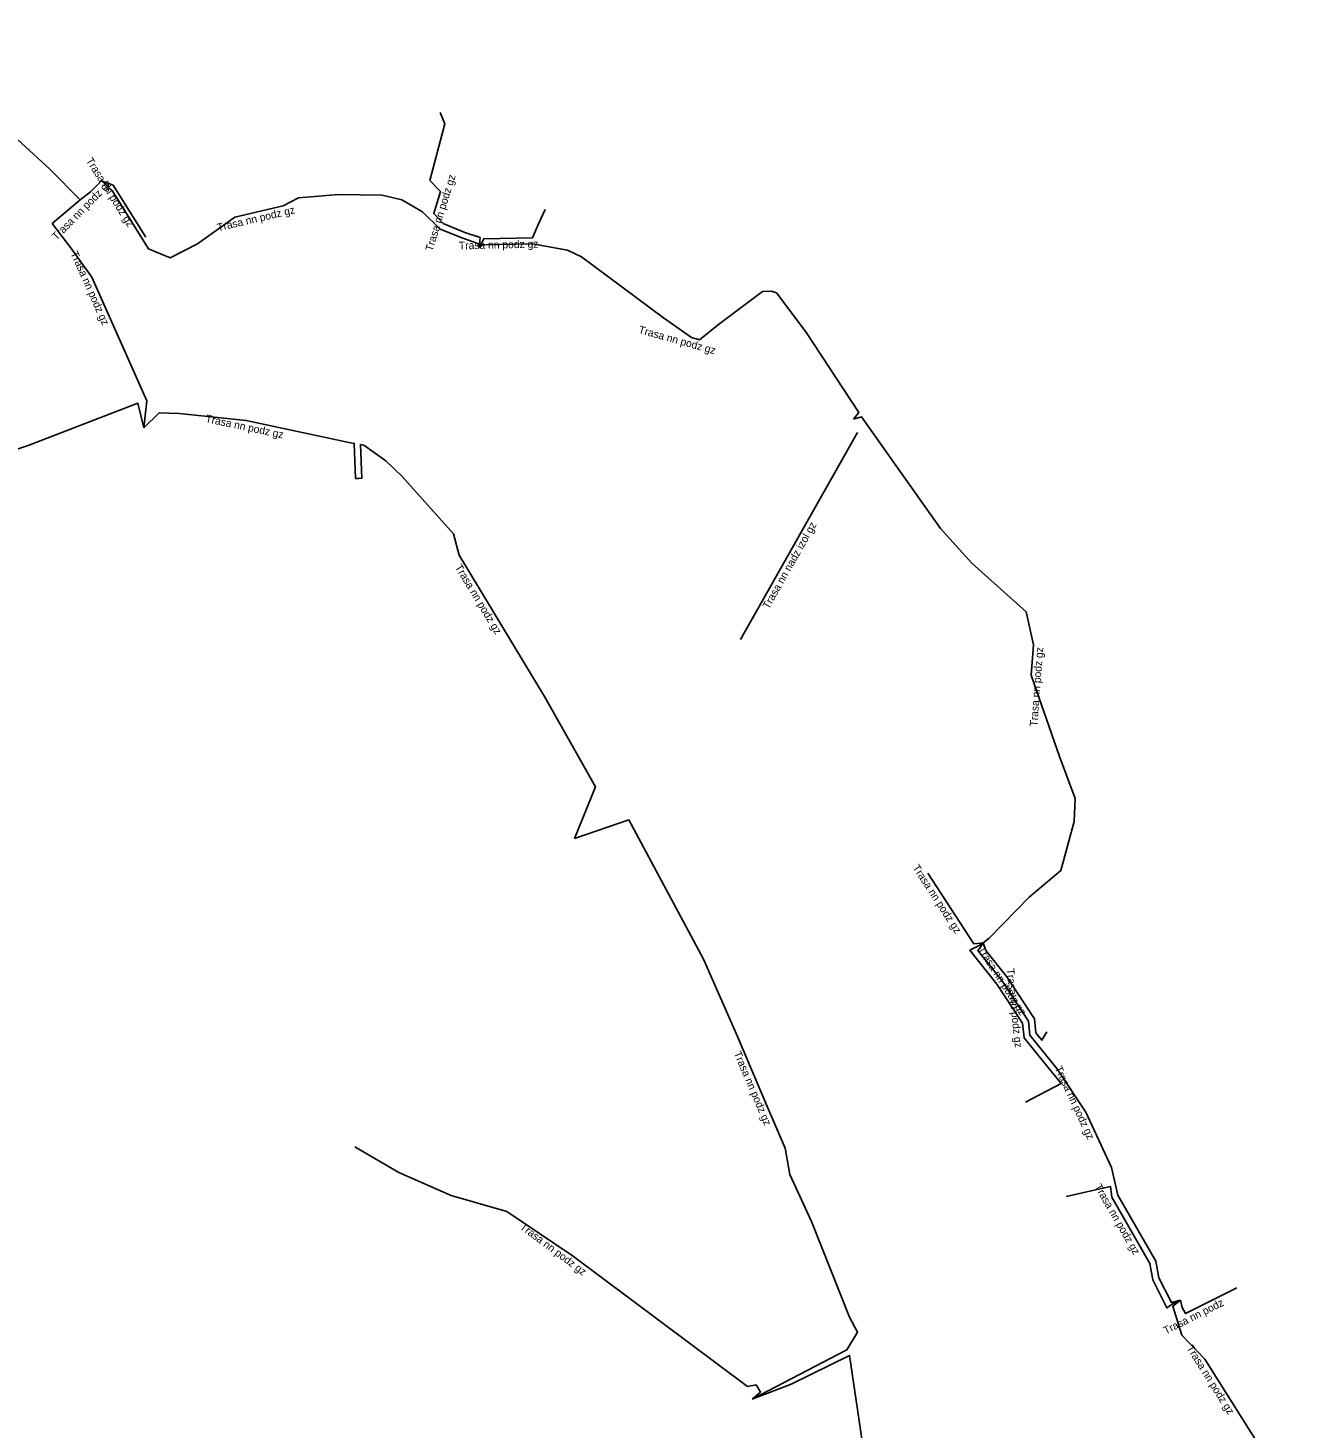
# Model space of a CAD drawing. Extents: x -484846 to -484244, y -1128177 to -1127608.
# Drawn here: x -484754.1 to -484671.6, y -1127724.5 to -1127633.5 of the extents above; entities that cross this region are included whole.
import ezdxf

# ---------------------------------------------------------------- set-up
doc = ezdxf.new("R2010")
doc.units = 0
doc.layers.add('Popiskový text - Ostatní atributy Trasy', color=7, linetype='Continuous')
doc.layers.add('Spojnice NN', color=7, linetype='Continuous')

msp = doc.modelspace()

# ---------------------------------------------------------------- linework, layer by layer
at = {"layer": 'Spojnice NN'}
for points in [[(-484761.387, -1127633.535), (-484759.01, -1127636.37), (-484755.62, -1127640.04), (-484752.72, -1127642.7), (-484750.74, -1127644.7)], [(-484724.81, -1127647.796), (-484724.758, -1127647.149), (-484725.74, -1127646.813), (-484727.151, -1127646.244), (-484727.767, -1127645.587), (-484727.33, -1127644.16), (-484728.02, -1127643.45), (-484727.05, -1127639.77), (-484727.341, -1127639.028)], [(-484750.74, -1127644.7), (-484750.06, -1127644.19), (-484749.35, -1127643.47)], [(-484724.81, -1127647.796), (-484724.894, -1127647.54), (-484725.88, -1127647.187), (-484727.349, -1127646.596), (-484728.5, -1127645.49), (-484729.83, -1127644.71), (-484731.12, -1127644.39), (-484733.98, -1127644.36), (-484734.73, -1127644.42), (-484736.56, -1127644.58), (-484737.55, -1127645.09), (-484740.69, -1127645.83), (-484743.11, -1127647.55), (-484744.9, -1127648.47), (-484746.29, -1127647.89), (-484748.656, -1127644.084), (-484749.35, -1127643.47)], [(-484749.35, -1127643.47), (-484748.606, -1127643.743), (-484746.469, -1127647.115)], [(-484750.74, -1127644.7), (-484752.57, -1127646.24), (-484751.3, -1127647.89), (-484749.98, -1127649.72), (-484746.419, -1127657.755), (-484746.597, -1127659.523)], [(-484724.81, -1127647.796), (-484724.516, -1127647.233), (-484721.354, -1127647.16), (-484720.95, -1127646.26), (-484720.533, -1127645.328)], [(-484700.5, -1127658.96), (-484700.148, -1127658.519), (-484703.58, -1127653.27), (-484705.5, -1127650.74), (-484705.83, -1127650.64), (-484706.4, -1127650.66), (-484709.27, -1127652.79), (-484710.51, -1127653.79), (-484711.01, -1127653.65), (-484712.84, -1127652.36), (-484718.16, -1127648.41), (-484719.07, -1127647.97), (-484721.346, -1127647.56), (-484724.576, -1127647.63), (-484724.81, -1127647.796)], [(-484746.597, -1127659.523), (-484747.004, -1127657.903), (-484754.11, -1127660.67), (-484759.19, -1127662.37), (-484767.82, -1127665.58), (-484773.69, -1127668), (-484774.44, -1127668.25), (-484774.56, -1127668.63)], [(-484746.597, -1127659.523), (-484745.598, -1127658.548), (-484744.3, -1127658.59), (-484739.95, -1127659.04), (-484733.18, -1127660.48), (-484732.932, -1127660.525), (-484732.842, -1127662.803), (-484732.642, -1127662.795)], [(-484692.073, -1127692.968), (-484691.676, -1127692.661), (-484689.09, -1127690.01), (-484687.02, -1127688.28), (-484686.15, -1127685.09), (-484686.09, -1127683.6), (-484687.11, -1127680.86), (-484688.95, -1127675.59), (-484688.8, -1127673.62), (-484689.28, -1127671.47), (-484692.81, -1127668.31), (-484694.83, -1127666.05), (-484699.97, -1127658.8), (-484700.5, -1127658.96)], [(-484700.24, -1127659.81), (-484707.841, -1127673.272)], [(-484732.642, -1127662.795), (-484732.442, -1127662.787), (-484732.529, -1127660.598), (-484732.3, -1127660.64), (-484730.88, -1127661.65), (-484729.82, -1127662.68), (-484726.49, -1127666.4), (-484726.12, -1127667.79), (-484720.58, -1127676.97), (-484717.26, -1127682.84), (-484718.617, -1127686.204)], [(-484718.617, -1127686.204), (-484715.09, -1127684.99), (-484710.23, -1127694.03), (-484708.04, -1127699.06), (-484706.15, -1127703.49), (-484704.94, -1127706.31), (-484704.64, -1127708.03), (-484703.23, -1127711.07), (-484700.75, -1127717.29), (-484700.23, -1127718.28), (-484700.929, -1127719.421), (-484707.084, -1127722.613)], [(-484695.67, -1127688.448), (-484692.683, -1127693.031), (-484692.44, -1127693.008), (-484692.073, -1127692.968)], [(-484689.312, -1127703.324), (-484687.001, -1127702.123), (-484688.782, -1127699.923), (-484689.415, -1127699.14), (-484689.517, -1127698.198), (-484691.175, -1127695.654), (-484692.929, -1127693.455), (-484692.276, -1127693.12), (-484692.073, -1127692.968)], [(-484679.249, -1127716.182), (-484679.834, -1127716.333), (-484680.658, -1127714.737), (-484680.849, -1127713.66), (-484683.326, -1127709.366), (-484683.73, -1127707.57), (-484685.39, -1127703.98), (-484687.29, -1127701.13), (-484689.03, -1127698.98), (-484689.13, -1127698.06), (-484690.85, -1127695.42), (-484692.408, -1127693.466), (-484692.29, -1127693.33), (-484692.073, -1127692.968)], [(-484687.936, -1127698.752), (-484688.256, -1127699.301), (-484688.645, -1127698.82), (-484688.743, -1127697.922), (-484690.525, -1127695.186), (-484691.887, -1127693.477), (-484692.073, -1127692.968)], [(-484732.891, -1127706.239), (-484730.04, -1127707.9), (-484726.64, -1127709.39), (-484723.02, -1127710.43), (-484718.77, -1127713.29), (-484707.39, -1127721.81), (-484706.82, -1127721.69), (-484706.534, -1127722.162), (-484707.084, -1127722.613)], [(-484679.249, -1127716.182), (-484679.599, -1127716.332), (-484680.136, -1127716.691), (-484681.042, -1127714.863), (-484681.231, -1127713.8), (-484683.714, -1127709.494), (-484683.791, -1127708.813), (-484686.68, -1127709.45)], [(-484679.249, -1127716.182), (-484679.141, -1127716.663), (-484678.932, -1127717.066), (-484675.585, -1127715.386)], [(-484671.612, -1127727.131), (-484672.309, -1127727.49), (-484672.71, -1127726.99), (-484673.83, -1127726.12), (-484677.66, -1127720.02), (-484679.17, -1127718.46), (-484679.741, -1127716.591), (-484679.249, -1127716.182)], [(-484707.084, -1127722.613), (-484704.534, -1127721.66), (-484700.751, -1127719.779), (-484699.7, -1127726.96), (-484698.97, -1127730.14), (-484697.97, -1127733.71), (-484696.29, -1127736.78), (-484696.31, -1127743.24), (-484696.97, -1127752.68), (-484697.396, -1127755.77), (-484694.663, -1127755.821), (-484687.685, -1127758.35), (-484686.76, -1127755.78)]]:
    msp.add_lwpolyline(points, dxfattribs=at)

# ---------------------------------------------------------------- texts
at = {"layer": 'Popiskový text - Ostatní atributy Trasy'}
for s, rotation, p in [('Trasa nn podz gz', 302.36331, (-484750.383, -1127642.153)), ('Trasa nn podz gz', 45.40066, (-484752.275, -1127647.361)), ('Trasa nn podz gz', 72.97348, (-484727.85, -1127648.078)), ('Trasa nn podz gz', 13.26086, (-484741.771, -1127646.752)), ('Trasa nn podz gz', 1.32253, (-484726.127, -1127647.921)), ('Trasa nn podz gz', 293.90357, (-484751.375, -1127648.177)), ('Trasa nn podz gz', 344.35775, (-484714.498, -1127653.348)), ('Trasa nn podz gz', 347.99197, (-484742.629, -1127659.134)), ('Trasa nn nadz izol gz', 60.54933, (-484705.999, -1127671.333)), ('Trasa nn podz gz', 301.11039, (-484726.41, -1127668.566)), ('Trasa nn podz gz', 85.64578, (-484688.552, -1127678.932)), ('Trasa nn podz gz', 303.09456, (-484696.679, -1127688.089)), ('Trasa nn podz gz', 303.07683, (-484692.46, -1127693.408)), ('Trasa nn podz gz', 276.17992, (-484690.553, -1127694.672)), ('Trasa nn podz gz', 293.10487, (-484708.285, -1127700.144)), ('Trasa nn podz gz', 294.81561, (-484687.43, -1127701.117)), ('Trasa nn podz gz', 299.96935, (-484684.855, -1127708.817)), ('Trasa nn podz gz', 323.17847, (-484722.212, -1127711.525)), ('Trasa nn podz', 26.65571, (-484680.203, -1127718.432)), ('Trasa nn podz gz', 302.12343, (-484678.877, -1127719.304))]:
    msp.add_text(s, height=0.5, rotation=rotation, dxfattribs=at).set_placement(p)

doc.saveas('drawing.dxf')
